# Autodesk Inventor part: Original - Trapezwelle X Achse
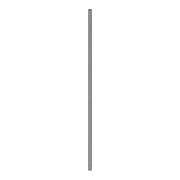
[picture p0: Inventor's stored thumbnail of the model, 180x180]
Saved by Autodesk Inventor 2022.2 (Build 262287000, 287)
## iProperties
Created: 2024-09
Part Number: Original - Trapezwelle X Achse
Material: Acciaio inossidabile
Document SubType Name: Modeling
Designer: 18907419
Density: 8 g/cm^3
Appearance: Semilucidato
Author: 18907419
Revision Number: ANY
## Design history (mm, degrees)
feature "Schnitt-Rotation1"
sketch "Schizzo1"
  geometry: L1 (-3.375, 11.321)-(23.093, 11.321); L2 (23.093, 11.321)-(23.093, -10.061); L3 (23.093, -10.061)-(-3.375, -10.061); L4 (-3.375, -10.061)-(-3.375, 11.321); 1 further point
  constraints: 8 end point
extrude "Estrusione1" cut sketch "Schizzo1" distance "d0" = 10; taper "d1" = 0 deg
sketch "Schizzo2"
  geometry: L1 (4, 16.716)-(4, 15.834) reference; L2 (4, 18.716)-(4, 17.834) reference; L3 (3.5, 15.508)-(3.5, 15.042) reference; L4 (4, 2.716)-(4, 1.834) reference; L5 (3.2, 0)-(-3.2, 0) reference; 5 further points
  constraints: 4 midpoint
  dimensions: "d2" = 2 distance of point (4, 16.275) point (4, 18.275) (derived); "d3" = 0.5 distance between parallel lines of L3 L1 (derived); "d4" = 4 horizontal distance of point (4, 2.275) point (0, 0) (derived)
node "Solido1"
